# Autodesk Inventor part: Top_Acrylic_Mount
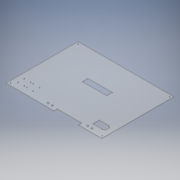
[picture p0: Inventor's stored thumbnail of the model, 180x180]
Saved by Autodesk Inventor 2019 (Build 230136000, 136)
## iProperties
Created: 2019-05
Part Number: Top_Acrylic_Mount
Material: PET Plastic
Document SubType Name: Modeling
Designer: Jorian Bruslind
Density: 1.541 g/cm^3
Appearance: Polycarbonate - Clear
Author: Jorian Bruslind
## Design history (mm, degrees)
sketch "Sketch1"
  geometry: L1 (0, 0)-(433, 0); L2 (433, 0)-(433, -326); L3 (433, -326)-(0, -326); L4 (0, -326)-(0, 0)
  constraints: 8 end point, 2 parallel, 1 horizontal, 1 perpendicular
  dimensions: "d0" = 433 distance of L2.end L3.end; "d1" = 326 distance of L1.end L2.end
extrude "Extrusion1" new body sketch "Sketch1" distance "d2" = 3; taper "d3" = 0 deg
sketch "Sketch2"
  geometry: L1 (0, 0)-(0, 326) reference; L2 (0, 326)-(-10, 326); L3 (0, 326)-(-433, 326) reference; L4 (-10, 326)-(-10, 316); C1 r 1.75 at (-10, 316); C2 r 1.75 at (-423, 316); C3 r 1.75 at (-10, 11); C4 r 1.75 at (-423, 11)
  constraints: 4 centre point, 4 end point, 1 coincident, 1 horizontal, 1 perpendicular, 1 point on line, 1 vertical, 6 other
  dimensions: "d4" = 10 distance of L1.end L2.end; "d5" = 10 distance of L2.end L4.end; "d6" = 3.5 diameter of C1; "d9" = 413 distance of C1.centre C2.centre; "d12" = 305 distance of C1.centre C3.centre
extrude "Extrusion2" cut sketch "Sketch2" distance "d15" = 3; taper "d16" = 0 deg
sketch "Sketch3"
  geometry: L1 (-433, 0)-(0, 0) reference; L2 (0, 0)-(-156, 0); L3 (-156, 0)-(-156, 178.5); L4 (-156, 178.5)-(-266.2, 178.5); L5 (-266.2, 178.5)-(-266.2, 203.5); L6 (-266.2, 203.5)-(-156, 203.5); L7 (-156, 203.5)-(-156, 178.5)
  constraints: 12 end point, 2 parallel, 2 perpendicular, 1 horizontal, 1 point on line
  dimensions: "d17" = 156 distance of L1.end L2.end; "d18" = 178.5 distance of L2.end L3.end; "d19" = 90 deg angle of L2 L3 (derived); "d20" = 110.2 distance of L5.end L6.end; "d21" = 25 distance of L4.end L5.end
extrude "Extrusion3" cut sketch "Sketch3" distance "d22" = 3; taper "d23" = 0 deg
sketch "Sketch4"
  geometry: L1 (0, 0)-(-106, 0); L2 (-156, 178.5)-(-156, 203.5) reference; L3 (-106, 0)-(-216.2, 0); L4 (-216.2, 0)-(-216.2, 15); L5 (-216.2, 15)-(-106, 15); L6 (-106, 15)-(-106, 0)
  constraints: 10 end point, 2 parallel, 2 perpendicular, 1 horizontal
  dimensions: "d24" = 110.2 distance of L4.end L5.end; "d25" = 15 distance of L3.end L4.end
extrude "Extrusion5" cut sketch "Sketch4" distance "d28" = 3; taper "d29" = 0 deg
sketch "Sketch5"
  geometry: L1 (-35.5, 40)-(-74.3, 40); L2 (-74.3, 40)-(-74.3, 63.1); L3 (-74.3, 63.1)-(-35.5, 63.1); L4 (-106, 0)-(0, 0) reference; L5 (0, 0)-(0, 326) reference; L6 (-35.5, 40)-(-28.044, 44.05); L7 (-35.5, 40)-(-27.015, 40); L8 (-28.044, 44.05)-(-28.044, 59.05); L9 (-28.044, 59.05)-(-35.5, 63.1); L10 (-433, 0)-(-216.2, 0) reference; L11 (-216.2, 0)-(-216.2, 15) reference; L12 (-241.2, 10)-(-260.2, 10); L13 (-241.2, 25)-(-260.2, 25); L14 (-106, 15)-(-216.2, 15) reference; L15 (-161.1, 15)-(-161.1, 25); L16 (-77.3, 37)-(-34.738, 37); L17 (-34.738, 37)-(-25.044, 42.266); L18 (-25.044, 42.266)-(-25.044, 60.834); L19 (-25.044, 60.834)-(-34.738, 66.1); L20 (-34.738, 66.1)-(-77.3, 66.1); L21 (-77.3, 66.1)-(-77.3, 37); L22 (-260.2, 27)-(-241.2, 27); L23 (-241.2, 8)-(-260.2, 8); L24 (-81, 8)-(-62, 8); L25 (-62, 27)-(-81, 27); L26 (-433, 326)-(-433, 0) reference; L27 (-433, 25)-(-433, 26); L28 (-380.488, 30)-(-374.776, 30); L29 (-374.776, 30)-(-374.776, 26); C1 r 2 at (-409.063, 30); C2 r 2 at (-380.488, 30); C3 r 2 at (-409.063, 58.575); C4 r 2 at (-380.488, 58.575); C5 r 2 at (-369.063, 30); C6 r 2 at (-340.488, 30); C7 r 2 at (-340.488, 58.575); C8 r 2 at (-369.063, 58.575); C9 r 4 at (-260.2, 17.5); C10 r 4 at (-241.2, 17.5); C11 r 4 at (-81, 17.5); C12 r 4 at (-62, 17.5); A1 r 7.5 centre (-241.2, 17.5) between (-241.2, 10) and (-241.2, 25); A2 r 7.5 centre (-260.2, 17.5) between (-260.2, 25) and (-260.2, 10); A3 r 9.5 centre (-241.2, 17.5) between (-241.2, 8) and (-241.2, 27); A4 r 9.5 centre (-260.2, 17.5) between (-260.2, 27) and (-260.2, 8); A5 r 9.5 centre (-81, 17.5) between (-81, 27) and (-81, 8); A6 r 9.5 centre (-62, 17.5) between (-62, 8) and (-62, 27)
  constraints: 46 end point, 18 centre point, 12 point on circle, 10 symmetric about line, 6 horizontal, 5 perpendicular, 4 coincident, 3 vertical, 2 point on line, 1 equal length, 1 midpoint, 20 other
  dimensions: "d30" = 38.8 distance of L1.start L1.end; "d31" = 23.1 distance of L1.end L2.end; "d32" = 38.8 distance of L2.end L3.end; "d40" = 40 distance between parallel lines of L4 L1; "d41" = 35.5 distance from line of L5 L1.start; "d42" = 8.485 distance of L1.start L6.end; "d43" = 28.51 deg angle of L7 L6; "d44" = 15 distance of L6.end L8.end; "d48" = 25 distance from line of L11 A1.centre; "d49" = 7.5 radius of A1; "d50" = 15 distance of L12.start L13.start; "d51" = 19 distance of L12.start L12.end; "d52" = 19 distance of L13.start L13.end; "d53" = 10 distance between parallel lines of L12 L10; "d54" = 7.5 radius of A2; "d55" = 10 distance of L15.start L15.end; "d56" = 3 distance between parallel lines of L1 L16; "d57" = 2 distance between parallel lines of L13 L22; "d58" = 4 diameter of C1; "d59" = 1 distance of L27.start L27.end; "d62" = 28.575 distance of C1.centre L28.start; "d65" = 28.575 distance of C1.centre C3.centre; "d68" = 30 distance from line of L10 C1.centre; "d69" = 23.937 distance from line of L26 C1.centre; "d70" = 5.7125 distance of L28.start L28.end; "d71" = 4 distance of L28.end L29.end; "d74" = 8 diameter of C9; "d75" = 8 diameter of C10; "d76" = 8 diameter of C11; "d77" = 8 diameter of C12
extrude "Extrusion7" cut sketch "Sketch5" distance "d78" = 3; taper "d79" = 0 deg
body "Solid1"
